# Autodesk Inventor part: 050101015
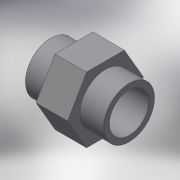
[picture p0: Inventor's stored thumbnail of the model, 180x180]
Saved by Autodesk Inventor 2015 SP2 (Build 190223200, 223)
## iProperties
Created: 2017-10
Part Number: 050101015
Material: Generic
Description: PLASSON THREADED SOCKET PVC 1.1/2"
Document SubType Name: Modeling
Designer: KIM
Density: 1 g/cm^3
Appearance: Default
Author: KIM
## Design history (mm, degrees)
derived "050101.ipt"
feature "Solid1::050101.ipt"
tag "TaggingFeature1"
body "Solid1"
other parameters: "d0" = 57, "d1" = 44.845, "d2" = 63, "d3" = 44.845, "d4" = 40.3605, "d5" = 22, "d6" = 22, "d7" = 58.2985, "d8" = 58.2985, "d10" = 15.4, "d13" = 0, "d14" = 0.44845, "d15" = 16, "G_" = 44.845, "C_" = 63, "B_" = 16, "lt_" = 22, "H_" = 57
